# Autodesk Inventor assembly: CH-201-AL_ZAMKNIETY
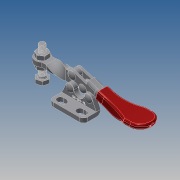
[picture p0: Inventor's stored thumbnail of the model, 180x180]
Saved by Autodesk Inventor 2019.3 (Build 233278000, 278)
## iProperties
Company: ·L?¤¤?
Created: 2010-06
Part Number: CH-201-AL_ZAMKNIETY
Material: Ogólny
Description: STEP AP203
Document SubType Name: Assembly
Designer: CADENGINEERING4
Sending System: SolidWorks 2005179
Preprocessor: SwSTEP 2.0
Title: CH-201-AL.STEP
Author: ·L?¥Î?
Revision Number: ANY
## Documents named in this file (8)
- E:\STRONA\Horizontal toggle clamp\CH-201-AL\CH-201-AL_ZAMKNIETY.iam
- E:\STRONA\Horizontal toggle clamp\CH-201-AL\201-AL-01___.ipt
- E:\STRONA\Horizontal toggle clamp\CH-201-AL\M4___.ipt
- E:\STRONA\Horizontal toggle clamp\CH-201-AL\201-A-02___.ipt
- E:\STRONA\Horizontal toggle clamp\CH-201-AL\201-06___.ipt
- E:\STRONA\Horizontal toggle clamp\CH-201-AL\CH-SA-042007___.ipt
- E:\STRONA\Horizontal toggle clamp\CH-201-AL\201-A-04___.ipt
- E:\STRONA\Horizontal toggle clamp\CH-201-AL\201-03___.iam
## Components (12 placed, 12 different names)
1. 201-AL-01_??_1 — Zestawiające:8, Zestawiające:9, Zestawiające:13, Zestawiające:14, Zestawiające:15, Zestawiające:16, Przejściowe:1
2. M4_??_2 — Równoległe:1, Zestawiające:2, Zestawiające:4
3. 201-A-02_??_3 — Zestawiające:1, Zestawiające:2, Zestawiające:3, Zestawiające:21, Zestawiające:22, Zestawiające:23
4. 201-06_??_4 — Zestawiające:17, Zestawiające:18, Zestawiające:19
5. CH-SA-042007_??_5 — Równoległe:1, Zestawiające:1, Zestawiające:4, Zestawiające:5
6. M4_??_6 — Zestawiające:3, Zestawiające:5
7. 201-06_??_7 — Zestawiające:6, Zestawiające:7, Zestawiające:22
8. 201-06_??_8 — Zestawiające:8, Zestawiające:9, Zestawiające:23
9. 201-06_??_9 — Zestawiające:15, Zestawiające:16
10. 201-A-04_??_10 — Zestawiające:10, Zestawiające:11, Zestawiające:12, Zestawiające:13, Zestawiające:17, Zestawiające:20
11. 201-03_??_11 [sub-assembly] — Zestawiające:6, Zestawiające:7, Zestawiające:18, Zestawiające:19, Zestawiające:20, Zestawiające:21, Przejściowe:1
12. 201-A-04_??_12 — Zestawiające:10, Zestawiające:11, Zestawiające:12, Zestawiające:14
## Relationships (25: Mate 23, Flush 1, Transitional 1)
- Równoległe:1 [Flush]: M4_??_2 ↔ CH-SA-042007_??_5
- Zestawiające:1 [Mate]: 201-A-02_??_3 ↔ CH-SA-042007_??_5
- Zestawiające:2 [Mate]: M4_??_2 ↔ 201-A-02_??_3
- Zestawiające:3 [Mate]: 201-A-02_??_3 ↔ M4_??_6
- Zestawiające:4 [Mate]: M4_??_2 ↔ CH-SA-042007_??_5
- Zestawiające:5 [Mate]: CH-SA-042007_??_5 ↔ M4_??_6
- Zestawiające:6 [Mate]: 201-06_??_7 ↔ 201-03_??_11
- Zestawiające:7 [Mate]: 201-06_??_7 ↔ 201-03_??_11
- Zestawiające:8 [Mate]: 201-AL-01_??_1 ↔ 201-06_??_8
- Zestawiające:9 [Mate]: 201-AL-01_??_1 ↔ 201-06_??_8
- Zestawiające:10 [Mate]: 201-A-04_??_10 ↔ 201-A-04_??_12
- Zestawiające:11 [Mate]: 201-A-04_??_10 ↔ 201-A-04_??_12
- Zestawiające:12 [Mate]: 201-A-04_??_10 ↔ 201-A-04_??_12
- Zestawiające:13 [Mate]: 201-AL-01_??_1 ↔ 201-A-04_??_10
- Zestawiające:14 [Mate]: 201-AL-01_??_1 ↔ 201-A-04_??_12
- Zestawiające:15 [Mate]: 201-AL-01_??_1 ↔ 201-06_??_9
- Zestawiające:16 [Mate]: 201-AL-01_??_1 ↔ 201-06_??_9
- Zestawiające:17 [Mate]: 201-06_??_4 ↔ 201-A-04_??_10
- Zestawiające:18 [Mate]: 201-06_??_4 ↔ 201-03_??_11
- Zestawiające:19 [Mate]: 201-06_??_4 ↔ 201-03_??_11
- Zestawiające:20 [Mate]: 201-A-04_??_10 ↔ 201-03_??_11
- Zestawiające:21 [Mate]: 201-A-02_??_3 ↔ 201-03_??_11
- Zestawiające:22 [Mate]: 201-A-02_??_3 ↔ 201-06_??_7
- Zestawiające:23 [Mate]: 201-A-02_??_3 ↔ 201-06_??_8
- Przejściowe:1 [Transitional]: 201-AL-01_??_1 ↔ 201-03_??_11
